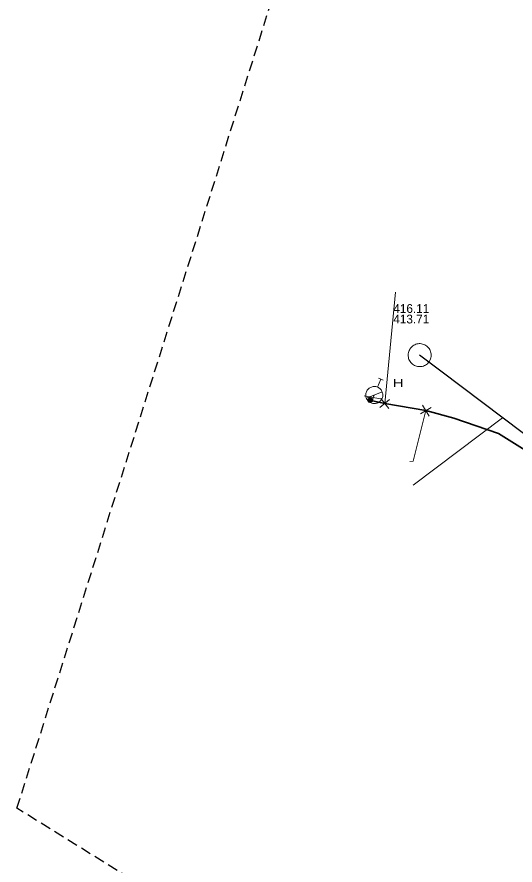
# Model space of a CAD drawing. Extents: x -772952 to -772403, y -1033777 to -1033210.
# Drawn here: x -772951.7 to -772900.6, y -1033589.9 to -1033502.9 of the extents above; entities that cross this region are included whole.
import ezdxf

# ---------------------------------------------------------------- set-up
doc = ezdxf.new("R2010")
doc.units = 0
doc.header["$LTSCALE"] = 0.36
doc.linetypes.add('MEDIUM_DASHED', pattern=[4.5, 3, -1.5])
for name, color, linetype, lineweight in [('15', 7, 'Continuous', 13), ('16', 7, 'Continuous', 35), ('2', 7, 'Continuous', 25), ('20', 7, 'Continuous', 13), ('4', 7, 'Continuous', 13), ('57', 7, 'Continuous', 13), ('59', 7, 'Continuous', 13), ('62', 7, 'MEDIUM_DASHED', 25)]:
    doc.layers.add(name, color=color, linetype=linetype, lineweight=lineweight)
doc.layers.add('6', color=7, linetype='Continuous')

msp = doc.modelspace()

# ---------------------------------------------------------------- linework, layer by layer
at = {"layer": '15'}
for p, q in [((-772914.249, -1033542.123), (-772916.077, -1033541.768)), ((-772914.477, -1033542.958), (-772913.479, -1033542.14)), ((-772913.567, -1033543.051), (-772914.394, -1033542.046)), ((-772909.207, -1033542.949), (-772910.315, -1033543.61)), ((-772910.093, -1033542.722), (-772909.424, -1033543.839))]:
    msp.add_line(p, q, dxfattribs=at)
for points in [[(-772915.249, -1033542.21), (-772915.255, -1033542.158), (-772915.272, -1033542.108), (-772915.301, -1033542.064), (-772915.338, -1033542.027), (-772915.383, -1033542), (-772915.433, -1033541.983), (-772915.486, -1033541.979), (-772915.538, -1033541.986), (-772915.587, -1033542.005), (-772915.63, -1033542.034), (-772915.666, -1033542.073), (-772915.692, -1033542.118), (-772915.708, -1033542.169), (-772915.711, -1033542.221), (-772915.703, -1033542.273), (-772915.683, -1033542.322), (-772915.652, -1033542.365), (-772915.613, -1033542.399), (-772915.567, -1033542.425), (-772915.516, -1033542.439), (-772915.463, -1033542.441), (-772915.412, -1033542.431), (-772915.364, -1033542.41), (-772915.321, -1033542.379), (-772915.287, -1033542.338), (-772915.263, -1033542.292), (-772915.25, -1033542.241)], [(-772915.279, -1033542.21), (-772915.285, -1033542.161), (-772915.302, -1033542.115), (-772915.33, -1033542.075), (-772915.367, -1033542.043), (-772915.411, -1033542.021), (-772915.459, -1033542.01), (-772915.508, -1033542.01), (-772915.554, -1033542.023), (-772915.598, -1033542.047), (-772915.634, -1033542.08), (-772915.661, -1033542.121), (-772915.677, -1033542.168), (-772915.681, -1033542.217), (-772915.674, -1033542.265), (-772915.655, -1033542.31), (-772915.625, -1033542.35), (-772915.587, -1033542.381), (-772915.543, -1033542.401), (-772915.495, -1033542.411), (-772915.446, -1033542.409), (-772915.399, -1033542.394), (-772915.356, -1033542.369), (-772915.321, -1033542.335), (-772915.296, -1033542.293), (-772915.282, -1033542.246)], [(-772915.309, -1033542.21), (-772915.315, -1033542.165), (-772915.331, -1033542.123), (-772915.36, -1033542.088), (-772915.396, -1033542.061), (-772915.438, -1033542.044), (-772915.483, -1033542.039), (-772915.527, -1033542.045), (-772915.569, -1033542.064), (-772915.603, -1033542.092), (-772915.63, -1033542.129), (-772915.647, -1033542.171), (-772915.651, -1033542.216), (-772915.644, -1033542.261), (-772915.625, -1033542.302), (-772915.596, -1033542.336), (-772915.559, -1033542.362), (-772915.516, -1033542.378), (-772915.471, -1033542.381), (-772915.426, -1033542.373), (-772915.386, -1033542.353), (-772915.352, -1033542.324), (-772915.326, -1033542.286), (-772915.312, -1033542.243)], [(-772915.339, -1033542.21), (-772915.343, -1033542.169), (-772915.362, -1033542.132), (-772915.389, -1033542.101), (-772915.424, -1033542.08), (-772915.464, -1033542.069), (-772915.505, -1033542.071), (-772915.544, -1033542.084), (-772915.578, -1033542.108), (-772915.603, -1033542.14), (-772915.618, -1033542.178), (-772915.62, -1033542.219), (-772915.613, -1033542.259), (-772915.593, -1033542.295), (-772915.564, -1033542.324), (-772915.527, -1033542.343), (-772915.487, -1033542.351), (-772915.446, -1033542.347), (-772915.407, -1033542.332), (-772915.375, -1033542.306), (-772915.353, -1033542.272), (-772915.34, -1033542.233)], [(-772915.369, -1033542.21), (-772915.374, -1033542.174), (-772915.392, -1033542.142), (-772915.418, -1033542.117), (-772915.451, -1033542.102), (-772915.488, -1033542.099), (-772915.522, -1033542.107), (-772915.554, -1033542.127), (-772915.576, -1033542.155), (-772915.59, -1033542.189), (-772915.59, -1033542.226), (-772915.579, -1033542.261), (-772915.558, -1033542.29), (-772915.527, -1033542.311), (-772915.493, -1033542.321), (-772915.456, -1033542.319), (-772915.422, -1033542.305), (-772915.395, -1033542.282), (-772915.375, -1033542.25), (-772915.369, -1033542.215)], [(-772915.399, -1033542.21), (-772915.404, -1033542.179), (-772915.421, -1033542.153), (-772915.446, -1033542.136), (-772915.477, -1033542.129), (-772915.508, -1033542.133), (-772915.535, -1033542.15), (-772915.553, -1033542.174), (-772915.561, -1033542.205), (-772915.557, -1033542.235), (-772915.542, -1033542.263), (-772915.517, -1033542.282), (-772915.488, -1033542.291), (-772915.456, -1033542.288), (-772915.429, -1033542.274), (-772915.409, -1033542.25), (-772915.399, -1033542.221)], [(-772915.429, -1033542.21), (-772915.434, -1033542.186), (-772915.451, -1033542.168), (-772915.473, -1033542.159), (-772915.498, -1033542.162), (-772915.519, -1033542.176), (-772915.53, -1033542.198), (-772915.53, -1033542.223), (-772915.517, -1033542.244), (-772915.498, -1033542.258), (-772915.473, -1033542.261), (-772915.45, -1033542.252), (-772915.434, -1033542.234)], [(-772915.459, -1033542.21), (-772915.464, -1033542.195), (-772915.478, -1033542.189), (-772915.494, -1033542.193), (-772915.5, -1033542.207), (-772915.497, -1033542.222), (-772915.483, -1033542.231), (-772915.468, -1033542.228), (-772915.459, -1033542.216)]]:
    msp.add_lwpolyline(points, close=True, dxfattribs=at)
at = {"layer": '16'}
msp.add_lwpolyline([(-772871.79, -1033565.033), (-772876.199, -1033564.929), (-772886.309, -1033556.62), (-772899.019, -1033547.67), (-772902.3, -1033545.62), (-772906.89, -1033544.059), (-772909.76, -1033543.28), (-772913.98, -1033542.55), (-772915.23, -1033542.289), (-772915.48, -1033542.21)], dxfattribs=at)
at = {"layer": '2'}
msp.add_lwpolyline([(-772872.43, -1033566.313), (-772887.748, -1033554.729), (-772899.887, -1033545.543), (-772908.093, -1033539.332), (-772910.4, -1033537.587)], dxfattribs=at)
at = {"layer": '20'}
for p, q in [((-772914.719, -1033540.864), (-772914.379, -1033540.047)), ((-772914.629, -1033539.944), (-772914.129, -1033540.152)), ((-772914.25, -1033541.348), (-772915.868, -1033542.016))]:
    msp.add_line(p, q, dxfattribs=at)
msp.add_lwpolyline([(-772914.246, -1033542.019), (-772914.215, -1033541.934), (-772914.194, -1033541.846), (-772914.181, -1033541.753), (-772914.179, -1033541.664), (-772914.186, -1033541.572), (-772914.202, -1033541.48), (-772914.229, -1033541.394), (-772914.263, -1033541.308), (-772914.308, -1033541.229), (-772914.358, -1033541.153), (-772914.418, -1033541.083), (-772914.484, -1033541.019), (-772914.556, -1033540.963), (-772914.634, -1033540.915), (-772914.718, -1033540.876), (-772914.804, -1033540.844), (-772914.893, -1033540.823), (-772914.983, -1033540.811), (-772915.075, -1033540.81), (-772915.167, -1033540.817), (-772915.257, -1033540.834), (-772915.345, -1033540.858), (-772915.429, -1033540.894), (-772915.51, -1033540.936), (-772915.586, -1033540.989), (-772915.656, -1033541.049), (-772915.718, -1033541.114), (-772915.774, -1033541.188), (-772915.822, -1033541.266), (-772915.863, -1033541.348), (-772915.892, -1033541.434), (-772915.914, -1033541.522), (-772915.926, -1033541.615), (-772915.929, -1033541.704), (-772915.921, -1033541.796), (-772915.905, -1033541.887), (-772915.879, -1033541.974), (-772915.845, -1033542.06), (-772915.8, -1033542.139), (-772915.749, -1033542.215), (-772915.689, -1033542.285), (-772915.623, -1033542.349), (-772915.55, -1033542.403), (-772915.473, -1033542.453), (-772915.39, -1033542.492), (-772915.303, -1033542.523), (-772915.214, -1033542.543), (-772915.124, -1033542.557), (-772915.032, -1033542.558), (-772914.94, -1033542.551), (-772914.851, -1033542.534), (-772914.763, -1033542.51), (-772914.678, -1033542.474), (-772914.598, -1033542.431), (-772914.522, -1033542.379), (-772914.451, -1033542.319), (-772914.39, -1033542.254), (-772914.333, -1033542.18), (-772914.285, -1033542.102), (-772914.247, -1033542.021)], dxfattribs=at)
at = {"layer": '4'}
msp.add_lwpolyline([(-772909.22, -1033537.587), (-772909.226, -1033537.468), (-772909.244, -1033537.351), (-772909.273, -1033537.235), (-772909.314, -1033537.124), (-772909.366, -1033537.017), (-772909.429, -1033536.916), (-772909.502, -1033536.821), (-772909.583, -1033536.735), (-772909.673, -1033536.657), (-772909.771, -1033536.588), (-772909.874, -1033536.53), (-772909.983, -1033536.483), (-772910.097, -1033536.446), (-772910.213, -1033536.421), (-772910.331, -1033536.409), (-772910.45, -1033536.408), (-772910.569, -1033536.419), (-772910.685, -1033536.442), (-772910.799, -1033536.476), (-772910.909, -1033536.522), (-772911.014, -1033536.579), (-772911.112, -1033536.646), (-772911.203, -1033536.722), (-772911.286, -1033536.807), (-772911.36, -1033536.901), (-772911.424, -1033537.001), (-772911.478, -1033537.107), (-772911.521, -1033537.218), (-772911.553, -1033537.332), (-772911.572, -1033537.45), (-772911.58, -1033537.569), (-772911.576, -1033537.687), (-772911.56, -1033537.805), (-772911.532, -1033537.921), (-772911.493, -1033538.033), (-772911.442, -1033538.141), (-772911.381, -1033538.243), (-772911.31, -1033538.339), (-772911.23, -1033538.426), (-772911.141, -1033538.506), (-772911.045, -1033538.576), (-772910.942, -1033538.636), (-772910.834, -1033538.685), (-772910.721, -1033538.723), (-772910.605, -1033538.749), (-772910.487, -1033538.764), (-772910.368, -1033538.767), (-772910.25, -1033538.758), (-772910.132, -1033538.737), (-772910.018, -1033538.704), (-772909.908, -1033538.66), (-772909.802, -1033538.605), (-772909.703, -1033538.539), (-772909.61, -1033538.464), (-772909.526, -1033538.38), (-772909.451, -1033538.288), (-772909.385, -1033538.189), (-772909.329, -1033538.084), (-772909.285, -1033537.974), (-772909.251, -1033537.86), (-772909.23, -1033537.743), (-772909.22, -1033537.624)], close=True, dxfattribs=at)
at = {"layer": '57'}
msp.add_line((-772901.912, -1033544.009), (-772911.079, -1033550.919), dxfattribs=at)
at = {"layer": '59'}
msp.add_line((-772913.98, -1033542.55), (-772912.879, -1033531.129), dxfattribs=at)
for points in [[(-772915.23, -1033542.29), (-772915.163, -1033541.946), (-772915.054, -1033541.684)], [(-772909.76, -1033543.28), (-772911.059, -1033548.48), (-772911.42, -1033548.489)]]:
    msp.add_lwpolyline(points, dxfattribs=at)
at = {"layer": '62'}
msp.add_lwpolyline([(-772641.514, -1033776.98), (-772641.529, -1033776.987), (-772951.708, -1033584.106), (-772846.395, -1033249.938), (-772562.451, -1033323.146)], close=True, dxfattribs=at)

# ---------------------------------------------------------------- texts
at = {"layer": '20', "width": 1.45}
msp.add_text('H ', height=0.8, dxfattribs=at).set_placement((-772913.176, -1033540.853))
at = {"layer": '6'}
for s, p in [('416.11', (-772913.098, -1033533.254)), ('413.71', (-772913.098, -1033534.331))]:
    msp.add_text(s, height=0.9, dxfattribs=at).set_placement(p)

doc.saveas('drawing.dxf')
